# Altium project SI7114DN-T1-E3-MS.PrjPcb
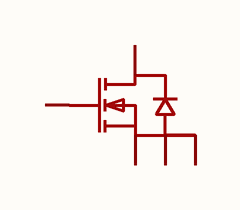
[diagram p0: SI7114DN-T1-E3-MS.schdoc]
1 sheet, 1 parts. Net scope: global (net labels, ports and power ports of the same name join across sheets).

## Sheet SI7114DN-T1-E3-MS.schdoc
size 127 x 101 mm

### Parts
Q?  si7114dn-t1-e3-ms  [DFN-8_L3.3-W3.3-P0.65-BL]  (value not drawn)

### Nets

Not connected (* = marked no-connect by the designer): Q? 1(S) 2(S) 3(S) 4(G) 5(D)

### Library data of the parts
Q? = si7114dn-t1-e3-ms: 数量:1个N沟道;漏源电压(Vdss):30V;连续漏极电流(Id):60A;导通电阻(RDS(on)):6mΩ@10V;耗散功率(Pd):59W;阈值电压(Vgs(th)):1.2V;; Manufacturer: MSKSEMI(美森科); AddInBom: yes; ModelId: f0059a17dd8f409ba5a4c367eb8306e1; ModelTransform: 129.921,129.99974,0,0,0,0,0.002,31.498,0; Number: 1个N沟道; Drain to Source Voltage: 30V; Current - Continuous Drain(Id): 60A; Pd - Power Dissipation: 59W; Gate Threshold Voltage (Vgs(th)): 1.2V; Gate Charge(Qg): 20nC; Input Capacitance(Ciss): 2.295nF; Reverse Transfer Capacitance (Crss@Vds): 210pF; Configuration: 独立式; Type: N沟道; Output Capacitance(Coss): 267pF; Vgs: ±20V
